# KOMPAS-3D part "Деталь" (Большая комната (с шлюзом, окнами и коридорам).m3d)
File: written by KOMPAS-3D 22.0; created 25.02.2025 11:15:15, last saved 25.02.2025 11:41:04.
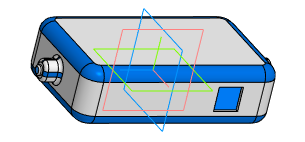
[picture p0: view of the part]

Document properties: Автор: Пользователь Windows; Полное имя файла: C:\Users\Student\Documents\Картошечка\База Сабнатика\Большая комната\Большая комната (с шлюзом, окнами и коридорам).m3d

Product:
- Body: Тело 1
    Масса: 2.227738
- Part/product: Деталь
    Масса: 2.240501

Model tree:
1. Эскиз:1
2. Элемент выдавливания:1
     Расстояние 1 = 35
3. Скругление:2  (with: Элемент выдавливания:1)
     Радиус = 10
4. Скругление:1  (with: Элемент выдавливания:1)
     Радиус = 7
5. Эскиз:2  (with: Элемент выдавливания:1)
6. Элемент выдавливания:2
     Расстояние 1 = 10
7. Скругление:3  (with: Элемент выдавливания:2)
     Радиус = 2
8. Эскиз:3  (with: Элемент выдавливания:2)
9. Элемент выдавливания:3
     Расстояние 1 = 2
10. Скругление:4  (with: Элемент выдавливания:3)
     Радиус = 1
11. Скругление:5  (with: Элемент выдавливания:2)
     Радиус = 2
12. Эскиз:4  (with: Элемент выдавливания:1, Скругление:1)
13. Элемент выдавливания:4
     Расстояние 2 = 2
14. Эскиз:5  (with: Элемент выдавливания:1, Скругление:1)
15. Элемент выдавливания:5
     Расстояние 2 = 2
16. Эскиз:6  (with: Элемент выдавливания:1)
17. Элемент выдавливания:6
     Расстояние 1 = 10
18. Скругление:6  (with: Элемент выдавливания:6)
     Радиус = 2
